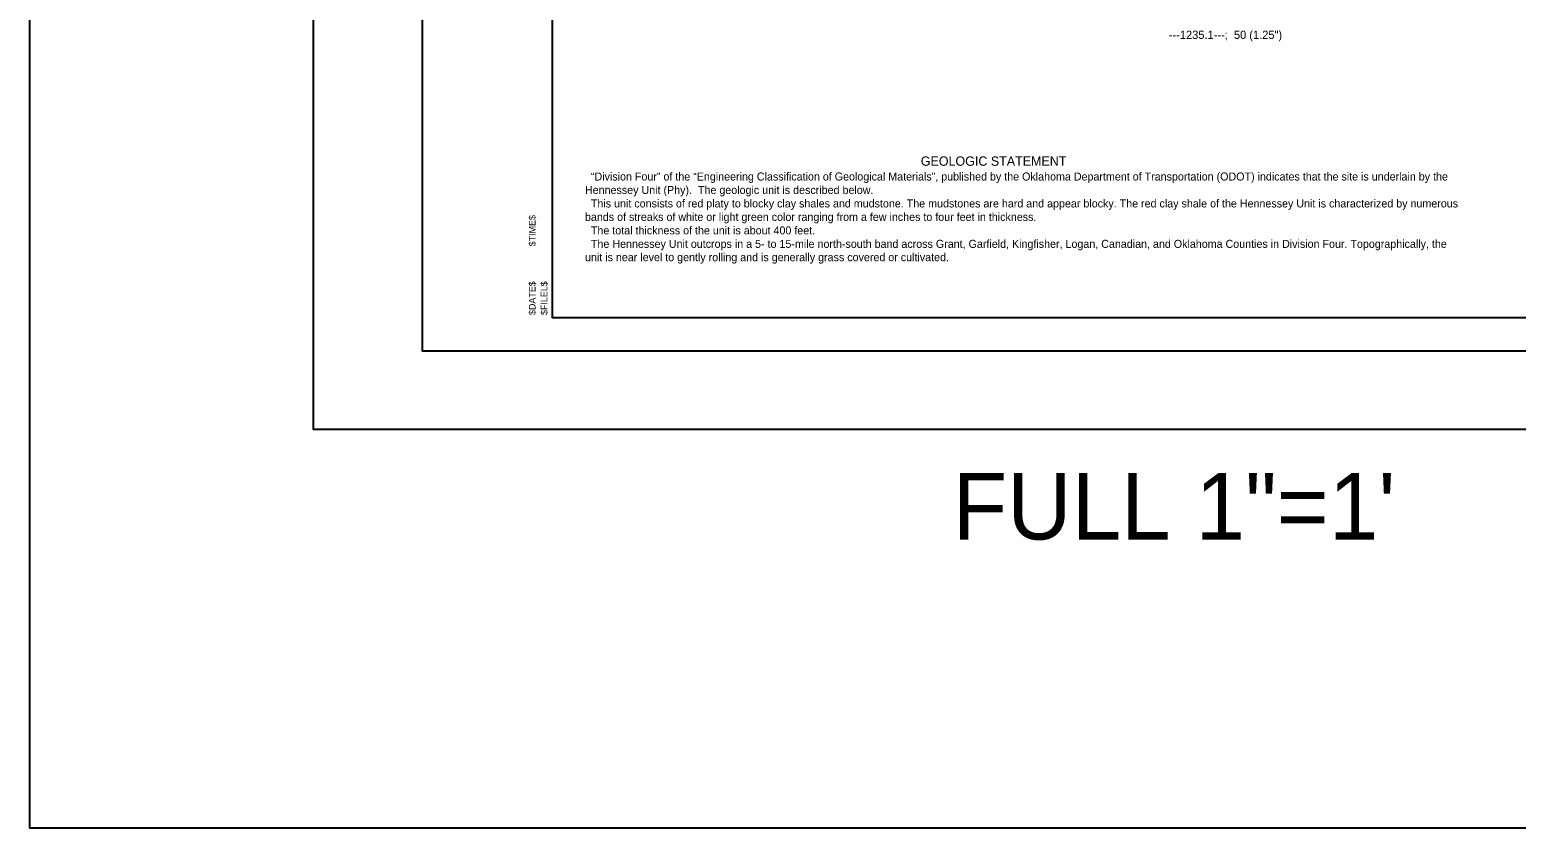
# Model space of a CAD drawing. Extents: x 2150148.6 to 2150220.1, y 143803.7 to 143875.1.
# Drawn here: x 2150160.32 to 2150182.61, y 143803.71 to 143815.68 of the extents above; entities that cross this region are included whole.
import ezdxf

# ---------------------------------------------------------------- set-up
doc = ezdxf.new("R2010")
doc.units = 0
for name, color, linetype in [('Default', 7, 'Continuous'), ('S', 7, 'Continuous'), ('SHT_Plot_Shape_Full', 7, 'Continuous'), ('SHT_Plot_Shape_Half', 7, 'Continuous'), ('SHT_Plot_Stamp', 7, 'Continuous'), ('SHT_Sheet_Border', 7, 'Continuous'), ('Text', 7, 'Continuous')]:
    doc.layers.add(name, color=color, linetype=linetype)

# ---------------------------------------------------------------- blocks, each defined once
blk = doc.blocks.new('Stamp_Plot_Stamp')
at = {"layer": 'SHT_Plot_Stamp'}
for s, p in [('$TIME$', (1.695, 1.572)), ('$DATE$', (1.695, 0.542)), ('$FILEL$', (1.873, 0.542))]:
    blk.add_text(s, height=0.1, rotation=90, dxfattribs=at).set_placement(p)

msp = doc.modelspace()

# ---------------------------------------------------------------- linework, layer by layer
at = {"layer": 'S'}
msp.add_lwpolyline([(2150160.321, 143875.14), (2150220.06, 143875.14), (2150220.06, 143803.708), (2150160.321, 143803.708)], close=True, dxfattribs=at)
at = {"layer": 'SHT_Plot_Shape_Full'}
msp.add_lwpolyline([(2150164.575, 143833.688), (2150200.575, 143833.688), (2150200.575, 143809.688), (2150164.575, 143809.688)], close=True, dxfattribs=at)
at = {"layer": 'SHT_Plot_Shape_Half'}
msp.add_lwpolyline([(2150166.212, 143832.863), (2150200.212, 143832.863), (2150200.212, 143810.863), (2150166.212, 143810.863)], close=True, dxfattribs=at)
at = {"layer": 'SHT_Sheet_Border'}
msp.add_lwpolyline([(2150199.662, 143811.363), (2150168.162, 143811.363), (2150168.162, 143832.363), (2150199.662, 143832.363)], close=True, dxfattribs=at)

# ---------------------------------------------------------------- block references
at = {"layer": 'SHT_Plot_Stamp'}
msp.add_blockref('Stamp_Plot_Stamp', (2150166.212, 143810.863), dxfattribs=at)

# ---------------------------------------------------------------- texts
at = {"layer": 'Default'}
msp.add_text('---1235.1---;  50 (1.25")', height=0.124, dxfattribs=at).set_placement((2150177.404, 143815.545))
at = {"layer": 'S'}
msp.add_text('FULL 1"=1\'', height=1, dxfattribs=at).set_placement((2150174.163, 143808.038))
at = {"layer": 'Text'}
for s, height, p in [('GEOLOGIC STATEMENT', 0.14, (2150173.684, 143813.643)), ('  “Division Four” of the “Engineering Classification of Geological Materials”, published by the Oklahoma Department of Transportation (ODOT) indicates that the site is underlain by the ', 0.12, (2150168.648, 143813.422)), ('Hennessey Unit (Phy).  The geologic unit is described below. ', 0.12, (2150168.648, 143813.22)), ('  This unit consists of red platy to blocky clay shales and mudstone. The mudstones are hard and appear blocky. The red clay shale of the Hennessey Unit is characterized by numerous ', 0.12, (2150168.648, 143813.018)), ('bands of streaks of white or light green color ranging from a few inches to four feet in thickness. ', 0.12, (2150168.648, 143812.816)), ('  The total thickness of the unit is about 400 feet.', 0.12, (2150168.648, 143812.614)), ('  The Hennessey Unit outcrops in a 5- to 15-mile north-south band across Grant, Garfield, Kingfisher, Logan, Canadian, and Oklahoma Counties in Division Four. Topographically, the ', 0.12, (2150168.648, 143812.412)), ('unit is near level to gently rolling and is generally grass covered or cultivated.', 0.12, (2150168.648, 143812.212))]:
    msp.add_text(s, height=height, dxfattribs=at).set_placement(p)

doc.saveas('drawing.dxf')
